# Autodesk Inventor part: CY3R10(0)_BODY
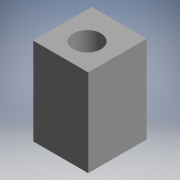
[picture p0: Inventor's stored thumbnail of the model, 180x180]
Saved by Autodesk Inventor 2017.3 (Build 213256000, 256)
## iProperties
Part Number: CY3R10(0)_BODY
Material: Generic
Catalog Web Link: www.cadenas.de
Description: CY3R BODY-Magnetically Coupled Rodless Cylinder Direct Mount Type
Vendor: SMC
Document SubType Name: Modeling
Designer: partserver
Manufacturer: SMC
Mass: 18.7949 g
Surface Area: 64.3642 cm^2
Volume: 18.7949 cm^3
Density: 1 g/cm^3
Appearance: PSOLRGB-191-191-191
Category: PARTsolutions
Company: SMC
Title: CY3R10_BODY
Author: Cadenas PARTsolutions
Comments: Magnetically Coupled Rodless Cylinder Direct Mount Type
PSOL_IDENT_0: {$CADENAS_DATA\23d-libs\smc_jp\actuator\rodless_cylinders\cy3\cy3r\parts\cy3r_body.prj},180 {VTYP=3D
PSOL_IDENT_1: },{NB=CY3R10(0)_BODY},{LINA=CY3R10_BODY},{NN=CY3R BODY},{DATE=09.12.2020 03:31:17},{GEOMDATE=10.09.2
PSOL_IDENT_2: 020 08:34:17},{VERSION=},{LINEID=20},{WBVAR=OMSC,THRADE2},{WBNUMERIC=}  {NB=CY3R10(0)_BODY},{LINA=CY
PSOL_IDENT_3: 3R10_BODY},{KT=DUMMY},{BORE=10},{OMSC=},{THRADE2=0},{D=12.0},{F=6.5},{HA=24},{GW=25.5},{K=9},{L=38},
PSOL_IDENT_4: {M=4.0},{MM=M3x0.5},{MRA=3},{MRP=0.50},{N=4.5},{TC=14.0},{W=20.0},{X=15},{S=5},{LA=15},{A=11.5}
NB: CY3R10(0)_BODY
NN: CY3R BODY
NT: Magnetically Coupled Rodless Cylinder Direct Mount Type
NBSYN: CY3R$BORE.$OMSC.($THRADE2.)_BODY
LINA: CY3R10_BODY
CATALOG: SMC (JP
BORE: 10
OMSC: (-) None
THRADE2: on
D: 12
F: 6.5
HA: 24
GW: 25.5
K: 9
L: 38
M: 4
MM: M3x0.5
N: 4.5
TC: 14
W: 20
X: 15
S: 5
LA: 15
A: 11.5
SUPPLIER: SMC
ARTICLENO: CY3R10(0)_BODY
BOMINFO: CY3R10_BODY
CREATOR: CADENAS GmbH
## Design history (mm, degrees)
sketch "Sketch_1"
  geometry: L1 (-12, -11.5)-(12, -11.5); L2 (12, -11.5)-(12, 14); L3 (12, 14)-(-12, 14); L4 (-12, 14)-(-12, -11.5); C1 r 6 at (0, 0); 1 further point
  constraints: 8 end point, 1 centre point
extrude "Extrusion1" join sketch "Sketch_1" distance "d0" = 38; taper "d1" = 0 deg
sketch "Sketch_2"
  geometry: L1 (12, 7.5)-(7.29, 7.5); L2 (7.29, 7.5)-(8, 8.729); L3 (8, 8.729)-(11.729, 8.729); L4 (11.729, 8.729)-(12, 9); L5 (12, 9)-(12, 7.5); L6 (12, 7.5)-(7.29, 7.5)
  constraints: 12 end point
revolve "Revolution1" sketch "Sketch_2" stored, may be unused: angle "d2" = 360 deg
thread "Thread1" dims "d3" = 3.7295, "d4" = 0
sketch "Sketch_3"
  geometry: L1 (7.5, 9.29)-(7.5, 14); L2 (7.5, 14)-(9, 14); L3 (9, 14)-(8.729, 13.73); L4 (8.729, 13.73)-(8.729, 10); L5 (8.729, 10)-(7.5, 9.29); L6 (7.5, 9.29)-(7.5, 14)
  constraints: 12 end point
revolve "Revolution2" sketch "Sketch_3" stored, may be unused: angle "d5" = 360 deg
thread "Thread2" dims "d6" = 3.7295, "d7" = 0
pattern_linear "Rectangular Pattern1" dims "d10" = 20, "d13" = 15
pattern_linear "Rectangular Pattern2" dims "d16" = 20, "d19" = 15
node "FF_XY"
node "FF_YZ"
node "FF_ZX"
node "FF_X"
node "FF_Y"
node "FF_Z"
node "FF_Center"
node "body_ct_XY"
node "body_ct_YZ"
node "body_ct_ZX"
node "body_ct_X"
node "body_ct_Y"
node "body_ct_Z"
node "body_ct_Center"
body "Solid1"
other parameters: "d20" = 0
